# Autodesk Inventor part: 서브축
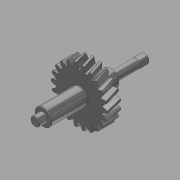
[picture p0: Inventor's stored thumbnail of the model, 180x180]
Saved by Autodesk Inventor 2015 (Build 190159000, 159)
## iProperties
Created: 2017-11
Part Number: 서브축
Material: 강철, 탄소
Document SubType Name: Modeling
Designer: mduedu
Categories: <?xml version="1.0" encoding="UTF-16"?> <MemberInstance><Categories><FamilyTemplate><FamilyTemplateParameter ValueType="xs:double" Id="1" ObjectReferenceKey="da
Density: 7.87 g/cm^3
Appearance: 반광택
Mass: 233.397 g
Surface Area: 98.1276 cm^2
Volume: 29.6566 cm^3
CustomPartVersion: 1
Author: mduedu
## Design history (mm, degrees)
sketch "Sketch1"
  geometry: C1 r 24.776 at (0, 0)
  constraints: 1 centre point
  dimensions: "d0" = 49.55215 diameter of C1 (= da_da)
extrude "Extrusion1" new body sketch "Sketch1" distance "d1" = 12 (= da_b); taper "d2" = 0 deg
workplane "Work Plane2"
sketch "Sketch2"
  geometry: C1 r 24.776 at (0, 0) reference; C2 r 22.776 at (0, 0)
  constraints: 1 centre point, 1 coincident
  dimensions: "d3" = 45.55215 diameter of C2 (= da_dw)
feature "피치 지름" sketch "Sketch2" dims "d4" = 10, "d5" = 0
workplane "Work Plane8"
workplane "Work Plane9"
feature "스퍼 기어" dims "da_b" = 12, "da_d" = 45.55215, "da_aw" = 54.86964, "da_da" = 49.55215, "da_df" = 40.55215, "da_dw" = 45.55215, angle "da_beta" = 15 deg, "da_lefttooth" = 10, "da_righttooth" = 0
sketch "스케치3"
  geometry: C1 r 7.5 at (0, 0); 1 further point
  constraints: 1 centre point, 1 coincident
  dimensions: "d49" = 15 diameter of C1
extrude "돌출2" join sketch "스케치3" distance "d50" = 32; taper "d51" = 0 deg
sketch "스케치4"
  geometry: C1 r 4 at (0, 0); 1 further point
  constraints: 1 centre point, 1 coincident
  dimensions: "d52" = 8 diameter of C1
extrude "돌출3" join sketch "스케치4" distance "d53" = 7; taper "d54" = 0 deg
sketch "스케치5"
  geometry: C1 r 7.5 at (0, 0); 1 further point
  constraints: 1 centre point, 1 coincident
  dimensions: "d55" = 15 diameter of C1
extrude "돌출4" join sketch "스케치5" distance "d56" = 16; taper "d57" = 0 deg
sketch "스케치6"
  geometry: C1 r 4 at (0, 0); 1 further point
  constraints: 1 centre point, 1 coincident
  dimensions: "d58" = 8 diameter of C1
extrude "돌출5" join sketch "스케치6" distance "d59" = 30; taper "d60" = 0 deg
chamfer "모따기1" distance "d61" = 0.5; stored, may be unused: second distance "d62" = 2, angle "d63" = 45 deg
fillet "모깎기1" dims "d64" = 0.5
sketch "스케치7"
  geometry: L1 (-3.25, -3.25)-(3.25, -3.25); L2 (3.25, -3.25)-(3.25, 3.25); L3 (3.25, 3.25)-(-3.25, 3.25); L4 (-3.25, 3.25)-(-3.25, -3.25); L5 (-3.25, -3.25)-(3.25, 3.25); L6 (3.25, -3.25)-(-3.25, 3.25); L7 (-5, -5)-(5, -5); L8 (5, -5)-(5, 5); L9 (5, 5)-(-5, 5); L10 (-5, 5)-(-5, -5); L11 (-5, -5)-(5, 5); L12 (5, -5)-(-5, 5); 1 further point
  constraints: 24 end point, 4 midpoint, 4 parallel, 2 horizontal, 2 perpendicular
  dimensions: "d65" = 6.5 distance of L3.end L2.end; "d66" = 6.5 distance of L2.end L1.end; "d67" = 10 distance of L9.end L8.end; "d68" = 10 distance of L8.end L7.end
extrude "돌출6" cut sketch "스케치7" distance "d69" = 8; taper "d70" = 0 deg
body "Solid1"
body "Srf1"
other parameters: "d16" = 54.86964 (= da_aw), "d17" = 0, "d34" = 1.428 (computed from da_z), "d39" = 0, "d41" = 0, "d43" = 54.86964 (= da_aw), "d46" = 54.86964 (= da_aw), "d47" = 0, "d48" = 0
